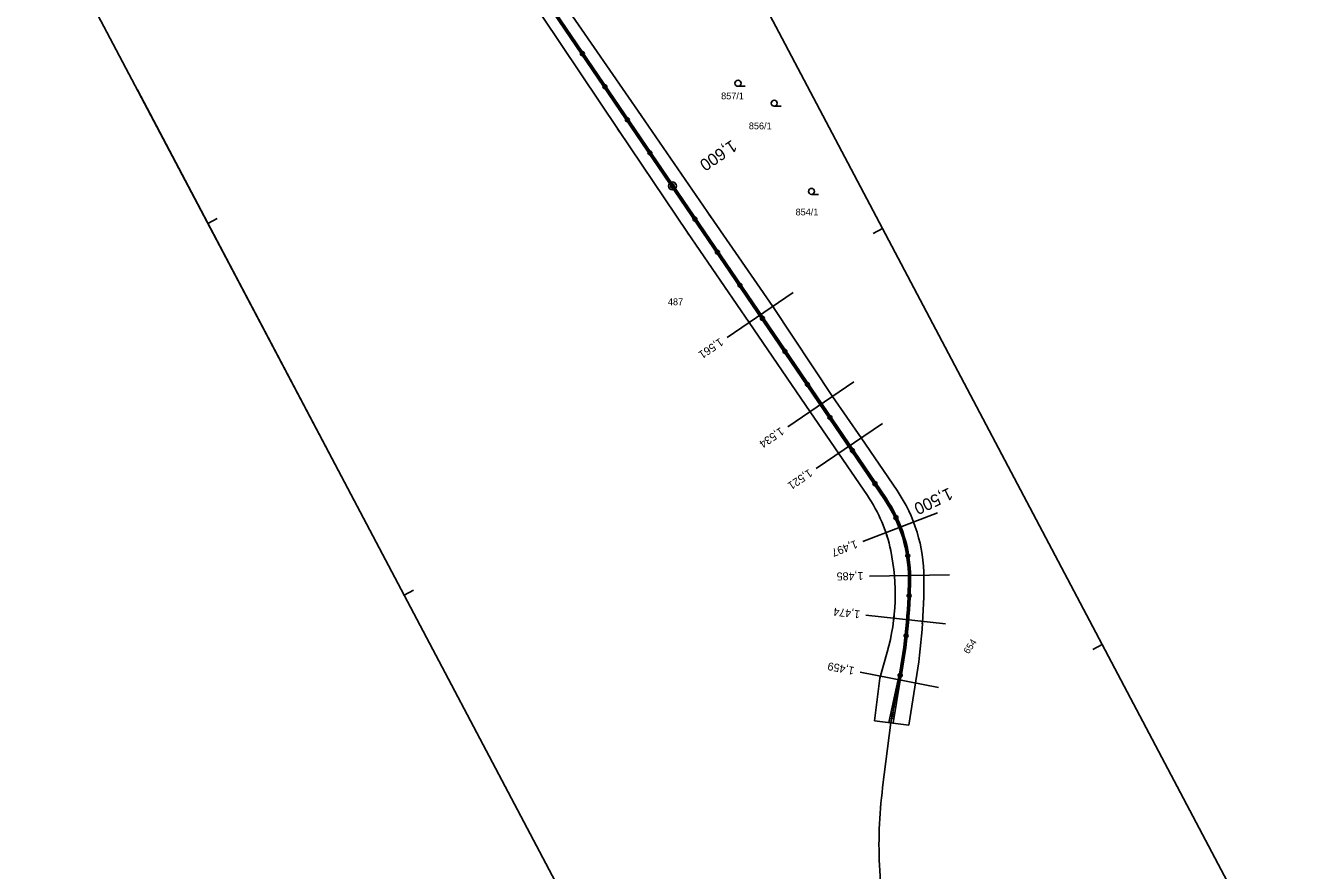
# Model space of a CAD drawing. Extents: x -548552 to -543113, y -1131925 to -1123599.
# Drawn here: x -547894.5 to -547576.1, y -1125450.3 to -1125239.2 of the extents above; entities that cross this region are included whole.
import ezdxf

# ---------------------------------------------------------------- set-up
doc = ezdxf.new("R2010")
doc.units = 0
for name, color, linetype in [('HRANY', 7, 'Continuous'), ('Parcelní čísla', 7, 'Continuous'), ('Poz předměty', 7, 'Continuous'), ('Profile', 7, 'Continuous'), ('PROFILY', 7, 'Continuous'), ('STANIČENÍ', 7, 'Continuous'), ('STANIČENÍ PROFILY', 7, 'Continuous'), ('Značky kultur', 7, 'Continuous')]:
    doc.layers.add(name, color=color, linetype=linetype)

msp = doc.modelspace()

# ---------------------------------------------------------------- linework, layer by layer
at = {"layer": 'HRANY'}
msp.add_line((-547673.73, -1125414.01), (-547682.3, -1125412.91), dxfattribs=at)
at = {"layer": 'Poz předměty'}
for p, q in [((-547679.86, -1125357.59), (-547789.9, -1125195.8)), ((-547679.45, -1125357.31), (-547789.49, -1125195.52)), ((-547740.66, -1125261.61), (-547760.22, -1125233.31)), ((-547765.35, -1125236.8), (-547746.25, -1125265.42)), ((-547723.27, -1125286.97), (-547740.66, -1125261.61)), ((-547746.25, -1125265.42), (-547729.05, -1125290.89)), ((-547707.73, -1125309.36), (-547723.27, -1125286.97)), ((-547729.05, -1125290.89), (-547713.62, -1125313.37)), ((-547692.82, -1125331.85), (-547707.73, -1125309.36)), ((-547713.62, -1125313.37), (-547698.44, -1125335.67)), ((-547692.82, -1125331.85), (-547685.64, -1125342.22)), ((-547698.44, -1125335.67), (-547684.08, -1125356.66)), ((-547685.64, -1125342.22), (-547676.68, -1125355.41)), ((-547679.15, -1125395.74), (-547680.96, -1125402.25)), ((-547680.96, -1125402.25), (-547682.3, -1125412.91)), ((-547676.38, -1125402.64), (-547678.73, -1125413.32)), ((-547675.89, -1125402.74), (-547677.7, -1125413.46)), ((-547676.38, -1125402.64), (-547676.31, -1125402.28)), ((-547675.89, -1125402.74), (-547675.82, -1125402.37)), ((-547671.98, -1125402.97), (-547673.73, -1125414.01))]:
    msp.add_line(p, q, dxfattribs=at)
for centre, radius, start, end in [((-547715.24, -1125377.96), 37.74, 11.6584, 34.3576), ((-547708.6, -1125377.13), 34.75, 359.7048, 34.2214), ((-547708.6, -1125377.13), 35, 359.7048, 34.2214), ((-547708.6, -1125377.13), 35.25, 359.7048, 34.2214), ((-547708.79, -1125377.22), 38.82, 0.1007, 34.1855), ((-547731.13, -1125381.24), 53.97, 344.4154, 11.6584), ((-547808.55, -1125376.62), 134.71, 349.0179, 359.7048), ((-547808.55, -1125376.62), 134.96, 349.0179, 359.7048), ((-547808.55, -1125376.62), 135.21, 349.0179, 359.7048), ((-547833.09, -1125377.44), 163.12, 350.9977, 0.1007)]:
    msp.add_arc(centre, radius, start, end, dxfattribs=at)
at = {"layer": 'Profile'}
for p, q in [((-547735.21, -1125185.94), (-547680.31, -1125289.91)), ((-547894.48, -1125202.33), (-547811.63, -1125359.25)), ((-547866.53, -1125255.27), (-547811.63, -1125359.25)), ((-547846.58, -1125287.41), (-547848.91, -1125288.64)), ((-547680.31, -1125289.91), (-547682.65, -1125291.15)), ((-547680.31, -1125289.91), (-547625.42, -1125393.89)), ((-547811.63, -1125359.25), (-547756.74, -1125463.22)), ((-547811.63, -1125359.25), (-547756.74, -1125463.22)), ((-547797.55, -1125380.26), (-547799.89, -1125381.49)), ((-547625.42, -1125393.89), (-547627.75, -1125395.12)), ((-547625.42, -1125393.89), (-547576.13, -1125487.24))]:
    msp.add_line(p, q, dxfattribs=at)
at = {"layer": 'PROFILY'}
for points in [[(-547719.16, -1125317.14), (-547702.63, -1125305.89)], [(-547703.99, -1125339.44), (-547687.46, -1125328.2)], [(-547696.9, -1125349.88), (-547680.36, -1125338.63)], [(-547685.28, -1125368.12), (-547666.61, -1125360.94)], [(-547683.6, -1125376.74), (-547663.6, -1125376.48)], [(-547684.46, -1125386.53), (-547664.57, -1125388.66)], [(-547685.95, -1125400.78), (-547666.32, -1125404.59)]]:
    msp.add_lwpolyline(points, dxfattribs=at)
at = {"layer": 'STANIČENÍ'}
for p, q in [((-547679.66, -1125357.45), (-547789.7, -1125195.66)), ((-547740.46, -1125261.92), (-547740.91, -1125261.25)), ((-547746.04, -1125265.74), (-547746.56, -1125264.97)), ((-547722.91, -1125287.51), (-547723.7, -1125286.34)), ((-547728.77, -1125291.3), (-547729.37, -1125290.41)), ((-547707.43, -1125309.8), (-547707.87, -1125309.16)), ((-547713.48, -1125313.58), (-547713.85, -1125313.04)), ((-547692.71, -1125332.02), (-547692.91, -1125331.72)), ((-547698.25, -1125335.95), (-547698.58, -1125335.46)), ((-547685.46, -1125342.48), (-547685.87, -1125341.88)), ((-547691.12, -1125346.37), (-547691.51, -1125345.8)), ((-547677.59, -1125388.09), (-547677.44, -1125386.67)), ((-547670.39, -1125388.73), (-547670.24, -1125387.4)), ((-547678.21, -1125413.39), (-547676.07, -1125402.33)), ((-547680.3, -1125429.62), (-547678.21, -1125413.39)), ((-547681.03, -1125450.35), (-547679.43, -1125478.33))]:
    msp.add_line(p, q, dxfattribs=at)
for centre, radius in [((-547759.83, -1125239.56), 0.1), ((-547759.27, -1125240.39), 0.1), ((-547758.71, -1125241.22), 0.1), ((-547758.15, -1125242.05), 0.1), ((-547757.58, -1125242.87), 0.1), ((-547757.02, -1125243.7), 0.1), ((-547756.46, -1125244.53), 0.1), ((-547755.9, -1125245.35), 0.1), ((-547755.33, -1125246.18), 0.5), ((-547755.33, -1125246.18), 0.1), ((-547754.77, -1125247.01), 0.1), ((-547754.21, -1125247.83), 0.1), ((-547753.65, -1125248.66), 0.1), ((-547753.08, -1125249.49), 0.1), ((-547752.52, -1125250.31), 0.1), ((-547751.96, -1125251.14), 0.1), ((-547751.4, -1125251.97), 0.1), ((-547750.83, -1125252.79), 0.1), ((-547750.27, -1125253.62), 0.1), ((-547749.71, -1125254.45), 0.5), ((-547749.71, -1125254.45), 0.1), ((-547749.15, -1125255.28), 0.1), ((-547748.59, -1125256.1), 0.1), ((-547748.02, -1125256.93), 0.1), ((-547747.46, -1125257.76), 0.1), ((-547746.9, -1125258.58), 0.1), ((-547746.34, -1125259.41), 0.1), ((-547745.77, -1125260.24), 0.1), ((-547745.21, -1125261.06), 0.1), ((-547744.65, -1125261.89), 0.1), ((-547744.09, -1125262.72), 0.5), ((-547744.09, -1125262.72), 0.1), ((-547743.52, -1125263.54), 0.1), ((-547742.96, -1125264.37), 0.1), ((-547742.4, -1125265.2), 0.1), ((-547741.84, -1125266.02), 0.1), ((-547741.27, -1125266.85), 0.1), ((-547740.71, -1125267.68), 0.1), ((-547740.15, -1125268.51), 0.1), ((-547739.59, -1125269.33), 0.1), ((-547739.02, -1125270.16), 0.1), ((-547738.46, -1125270.99), 0.5), ((-547738.46, -1125270.99), 0.1), ((-547737.9, -1125271.81), 0.1), ((-547737.34, -1125272.64), 0.1), ((-547736.78, -1125273.47), 0.1), ((-547736.21, -1125274.29), 0.1), ((-547735.65, -1125275.12), 0.1), ((-547735.09, -1125275.95), 0.1), ((-547734.53, -1125276.77), 0.1), ((-547733.96, -1125277.6), 0.1), ((-547732.84, -1125279.25), 1), ((-547733.4, -1125278.43), 0.1), ((-547732.84, -1125279.25), 0.5), ((-547732.84, -1125279.25), 0.1), ((-547732.28, -1125280.08), 0.1), ((-547731.71, -1125280.91), 0.1), ((-547731.15, -1125281.74), 0.1), ((-547730.59, -1125282.56), 0.1), ((-547730.03, -1125283.39), 0.1), ((-547729.46, -1125284.22), 0.1), ((-547728.9, -1125285.04), 0.1), ((-547728.34, -1125285.87), 0.1), ((-547727.78, -1125286.7), 0.1), ((-547727.21, -1125287.52), 0.5), ((-547727.21, -1125287.52), 0.1), ((-547726.65, -1125288.35), 0.1), ((-547726.09, -1125289.18), 0.1), ((-547725.53, -1125290), 0.1), ((-547724.96, -1125290.83), 0.1), ((-547724.4, -1125291.66), 0.1), ((-547723.84, -1125292.48), 0.1), ((-547723.28, -1125293.31), 0.1), ((-547722.72, -1125294.14), 0.1), ((-547722.15, -1125294.97), 0.1), ((-547721.59, -1125295.79), 0.5), ((-547721.59, -1125295.79), 0.1), ((-547721.03, -1125296.62), 0.1), ((-547720.47, -1125297.45), 0.1), ((-547719.9, -1125298.27), 0.1), ((-547719.34, -1125299.1), 0.1), ((-547718.78, -1125299.93), 0.1), ((-547718.22, -1125300.75), 0.1), ((-547717.65, -1125301.58), 0.1), ((-547717.09, -1125302.41), 0.1), ((-547716.53, -1125303.23), 0.1), ((-547715.97, -1125304.06), 0.5), ((-547715.97, -1125304.06), 0.1), ((-547715.4, -1125304.89), 0.1), ((-547714.84, -1125305.71), 0.1), ((-547714.28, -1125306.54), 0.1), ((-547713.72, -1125307.37), 0.1), ((-547713.15, -1125308.2), 0.1), ((-547712.59, -1125309.02), 0.1), ((-547712.03, -1125309.85), 0.1), ((-547711.47, -1125310.68), 0.1), ((-547710.91, -1125311.5), 0.1), ((-547710.34, -1125312.33), 0.5), ((-547710.34, -1125312.33), 0.1), ((-547709.78, -1125313.16), 0.1), ((-547709.22, -1125313.98), 0.1), ((-547708.66, -1125314.81), 0.1), ((-547708.09, -1125315.64), 0.1), ((-547707.53, -1125316.46), 0.1), ((-547706.97, -1125317.29), 0.1), ((-547706.41, -1125318.12), 0.1), ((-547705.84, -1125318.94), 0.1), ((-547705.28, -1125319.77), 0.1), ((-547704.72, -1125320.6), 0.5), ((-547704.72, -1125320.6), 0.1), ((-547704.16, -1125321.43), 0.1), ((-547703.59, -1125322.25), 0.1), ((-547703.03, -1125323.08), 0.1), ((-547702.47, -1125323.91), 0.1), ((-547701.91, -1125324.73), 0.1), ((-547701.34, -1125325.56), 0.1), ((-547700.78, -1125326.39), 0.1), ((-547700.22, -1125327.21), 0.1), ((-547699.66, -1125328.04), 0.1), ((-547699.09, -1125328.87), 0.5), ((-547699.09, -1125328.87), 0.1), ((-547698.53, -1125329.69), 0.1), ((-547697.97, -1125330.52), 0.1), ((-547697.41, -1125331.35), 0.1), ((-547696.85, -1125332.17), 0.1), ((-547696.28, -1125333), 0.1), ((-547695.72, -1125333.83), 0.1), ((-547695.16, -1125334.66), 0.1), ((-547694.6, -1125335.48), 0.1), ((-547694.03, -1125336.31), 0.1), ((-547693.47, -1125337.14), 0.5), ((-547693.47, -1125337.14), 0.1), ((-547692.91, -1125337.96), 0.1), ((-547692.35, -1125338.79), 0.1), ((-547691.78, -1125339.62), 0.1), ((-547691.22, -1125340.44), 0.1), ((-547690.66, -1125341.27), 0.1), ((-547690.1, -1125342.1), 0.1), ((-547689.53, -1125342.92), 0.1), ((-547688.97, -1125343.75), 0.1), ((-547688.41, -1125344.58), 0.1), ((-547687.85, -1125345.4), 0.5), ((-547687.85, -1125345.4), 0.1), ((-547687.28, -1125346.23), 0.1), ((-547686.72, -1125347.06), 0.1), ((-547686.16, -1125347.88), 0.1), ((-547685.6, -1125348.71), 0.1), ((-547685.04, -1125349.54), 0.1), ((-547684.47, -1125350.37), 0.1), ((-547683.91, -1125351.19), 0.1), ((-547683.35, -1125352.02), 0.1), ((-547682.79, -1125352.85), 0.1), ((-547682.22, -1125353.67), 0.5), ((-547682.22, -1125353.67), 0.1), ((-547681.66, -1125354.5), 0.1), ((-547681.1, -1125355.33), 0.1), ((-547680.54, -1125356.15), 0.1), ((-547679.97, -1125356.98), 0.1), ((-547679.41, -1125357.81), 0.1), ((-547678.87, -1125358.65), 0.1), ((-547678.36, -1125359.51), 0.1), ((-547677.87, -1125360.38), 0.1), ((-547677.4, -1125361.26), 0.1), ((-547676.96, -1125362.16), 0.5), ((-547676.96, -1125362.16), 0.1), ((-547676.54, -1125363.07), 0.1), ((-547676.16, -1125363.99), 0.1), ((-547675.79, -1125364.92), 0.1), ((-547675.46, -1125365.87), 0.1), ((-547675.15, -1125366.82), 0.1), ((-547674.87, -1125367.78), 0.1), ((-547674.62, -1125368.74), 0.1), ((-547674.39, -1125369.72), 0.1), ((-547674.19, -1125370.7), 0.1), ((-547674.02, -1125371.68), 0.5), ((-547674.02, -1125371.68), 0.1), ((-547673.88, -1125372.67), 0.1), ((-547673.77, -1125373.67), 0.1), ((-547673.68, -1125374.66), 0.1), ((-547673.63, -1125375.66), 0.1), ((-547673.6, -1125376.66), 0.1), ((-547673.66, -1125380.66), 0.1), ((-547673.63, -1125378.66), 0.1), ((-547673.63, -1125379.66), 0.1), ((-547673.6, -1125377.66), 0.1), ((-547673.69, -1125381.66), 0.5), ((-547673.78, -1125383.65), 0.1), ((-547673.73, -1125382.66), 0.1), ((-547673.69, -1125381.66), 0.1), ((-547673.97, -1125386.67), 0.1), ((-547673.9, -1125385.69), 0.1), ((-547673.84, -1125384.67), 0.1), ((-547674.23, -1125389.67), 0.1), ((-547674.13, -1125388.61), 0.1), ((-547674.05, -1125387.64), 0.1), ((-547674.44, -1125391.67), 0.5), ((-547674.56, -1125392.71), 0.1), ((-547674.44, -1125391.67), 0.1), ((-547674.33, -1125390.69), 0.1), ((-547674.94, -1125395.65), 0.1), ((-547674.81, -1125394.68), 0.1), ((-547674.68, -1125393.68), 0.1), ((-547675.57, -1125399.62), 0.1), ((-547675.4, -1125398.63), 0.1), ((-547675.24, -1125397.63), 0.1), ((-547675.09, -1125396.64), 0.1), ((-547675.92, -1125401.57), 0.5), ((-547676.12, -1125402.53), 0.1), ((-547675.92, -1125401.57), 0.1), ((-547675.74, -1125400.6), 0.1), ((-547676.68, -1125405.48), 0.1), ((-547676.49, -1125404.5), 0.1), ((-547676.3, -1125403.51), 0.1), ((-547677.25, -1125408.42), 0.1), ((-547677.06, -1125407.44), 0.1), ((-547676.87, -1125406.46), 0.1), ((-547677.82, -1125411.37), 0.5), ((-547678.01, -1125412.35), 0.1), ((-547677.82, -1125411.37), 0.1), ((-547677.63, -1125410.39), 0.1), ((-547677.44, -1125409.4), 0.1), ((-547678.2, -1125413.33), 0.1)]:
    msp.add_circle(centre, radius, dxfattribs=at)
for centre, radius, start, end in [((-547708.6, -1125377.13), 31.21, 19.1613, 22.081), ((-547708.6, -1125377.13), 38.63, 359.5575, 1.6086), ((-547568.88, -1125443.93), 112.33, 172.6782, 183.2724)]:
    msp.add_arc(centre, radius, start, end, dxfattribs=at)
at = {"layer": 'Značky kultur'}
for p, q in [((-547716.44, -1125254.35), (-547714.69, -1125254.35)), ((-547707.39, -1125259.33), (-547705.64, -1125259.33)), ((-547698.08, -1125281.37), (-547696.33, -1125281.37))]:
    msp.add_line(p, q, dxfattribs=at)
for centre in [(-547716.44, -1125253.6), (-547707.39, -1125258.58), (-547698.08, -1125280.62)]:
    msp.add_circle(centre, 0.75, dxfattribs=at)

# ---------------------------------------------------------------- texts
at = {"layer": 'Parcelní čísla'}
for s, p in [('857/1', (-547720.65, -1125257.61)), ('856/1', (-547713.73, -1125265.1)), ('854/1', (-547702.05, -1125286.62)), ('487', (-547733.95, -1125309.06))]:
    msp.add_text(s, height=1.7, dxfattribs=at).set_placement(p)
msp.add_text('654', height=1.7, rotation=56, dxfattribs=at).set_placement((-547658.83, -1125396.37))
at = {"layer": 'STANIČENÍ'}
for s, rotation, p in [('1,600', 214.2214, (-547718.01, -1125267.61)), ('1,500', 205.3528, (-547663.69, -1125354.56))]:
    msp.add_text(s, height=3, rotation=rotation, dxfattribs=at).set_placement(p)
at = {"layer": 'STANIČENÍ PROFILY'}
for s, rotation, p in [('1,561', 214.2214, (-547720.97, -1125317.16)), ('1,534', 214.2214, (-547705.8, -1125339.46)), ('1,521', 214.2214, (-547698.7, -1125349.9)), ('1,497', 201.0473, (-547687.04, -1125367.73)), ('1,485', 180.7343, (-547685.11, -1125375.76)), ('1,474', 173.878, (-547685.85, -1125385.37)), ('1,459', 169.0179, (-547687.24, -1125399.52))]:
    msp.add_text(s, height=2, rotation=rotation, dxfattribs=at).set_placement(p)

doc.saveas('drawing.dxf')
